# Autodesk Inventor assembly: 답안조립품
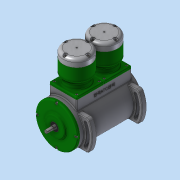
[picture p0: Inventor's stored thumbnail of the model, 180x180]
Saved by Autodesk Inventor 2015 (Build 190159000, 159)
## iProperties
Created: 2017-08
Part Number: 답안조립품
Document SubType Name: Assembly
Designer: SCD-A14
Author: SCD-A14
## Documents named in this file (16)
- C:\Users\SCD-A14\Desktop\370808V1008\답안조립품.iam
- C:\Users\SCD-A14\Desktop\370808V1008\본체.ipt
- C:\Users\SCD-A14\Desktop\370808V1008\너트 M4.ipt
- C:\Users\SCD-A14\Desktop\370808V1008\베어링 12 x 28 x 8.ipt
- C:\Users\SCD-A14\Desktop\370808V1008\볼트 M4 x 8.ipt
- C:\Users\SCD-A14\Desktop\370808V1008\볼트 M5 x 20.ipt
- C:\Users\SCD-A14\Desktop\370808V1008\실린더.ipt
- C:\Users\SCD-A14\Desktop\370808V1008\실린더헤드.ipt
- C:\Users\SCD-A14\Desktop\370808V1008\앞커버.ipt
- C:\Users\SCD-A14\Desktop\370808V1008\오일 실 12 25 7.ipt
- C:\Users\SCD-A14\Desktop\370808V1008\육각 머리 볼트 M4 x 16.ipt
- C:\Users\SCD-A14\Desktop\370808V1008\커넥팅로드 엔드.ipt
- C:\Users\SCD-A14\Desktop\370808V1008\커넥팅로드.ipt
- C:\Users\SCD-A14\Desktop\370808V1008\크랭크축.ipt
- C:\Users\SCD-A14\Desktop\370808V1008\피스톤.ipt
- C:\Users\SCD-A14\Desktop\370808V1008\피스톤핀.ipt
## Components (4 placed, 2 different names)
1. 피스톤:1
2. 피스톤핀:1
3. 피스톤:2
4. 피스톤핀:2
## Named parameters: d4_d1 = 0, d7_d0 = 0, d16_d12 = 0, d18_d14 = 0, d19_d15 = 0, d20_d4_d1 = 0, d23_d7_d0 = 0, d24_d11 = 0
